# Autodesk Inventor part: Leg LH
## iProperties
Created: 2010-08
Part Number: Leg LH
Material: Default
Document SubType Name: Modeling
Designer: Paul Munford
Density: 1 g/cm^3
Author: Paul Munford
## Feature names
1. TaggingFeature2
